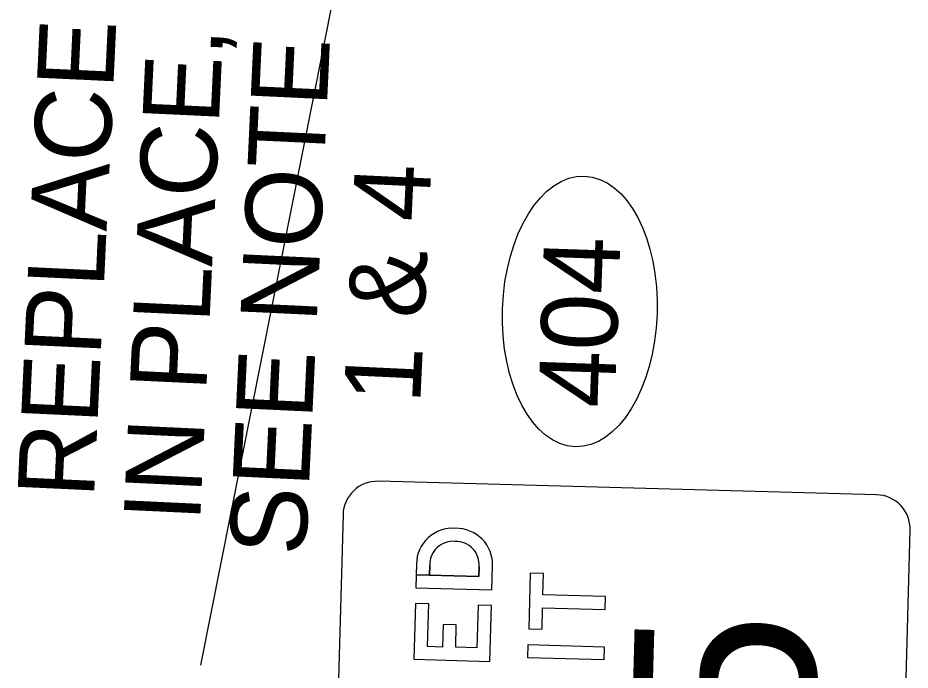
# Model space of a CAD drawing. Extents: x 2096670 to 2098561, y 684033 to 689893.
# Drawn here: x 2097308.7 to 2097448.6, y 687092.5 to 687194.8 of the extents above; entities that cross this region are included whole.
import ezdxf

# ---------------------------------------------------------------- set-up
doc = ezdxf.new("R2010")
doc.units = 0
for name, color, linetype in [('Prop DSN Text', 7, 'Continuous'), ('Prop Sign E Keep Right CELL', 7, 'Continuous'), ('Prop Sign E One Way_Right CELL', 7, 'Continuous'), ('Scratch_Level_3', 7, 'Continuous')]:
    doc.layers.add(name, color=color, linetype=linetype)

msp = doc.modelspace()

# ---------------------------------------------------------------- linework, layer by layer
at = {"layer": 'Prop Sign E Keep Right CELL'}
for p, q in [((2097443.4, 687120), (2097365.27, 687122.12)), ((2097359.73, 687116.87), (2097358.09, 687056.6)), ((2097447.01, 687054.19), (2097448.65, 687114.46)), ((2097381.02, 687107.2), (2097381.07, 687108.73)), ((2097383.05, 687105.09), (2097383.15, 687108.84))]:
    msp.add_line(p, q, dxfattribs=at)
for points in [[(2097371.25, 687109.17), (2097371.15, 687105.41), (2097383.05, 687105.09)], [(2097371.25, 687109.17), (2097371.2, 687107.46), (2097373.29, 687107.41), (2097373.33, 687108.94)], [(2097371.25, 687109.17), (2097371.2, 687107.46), (2097373.29, 687107.41), (2097373.33, 687108.94)], [(2097381.07, 687108.73), (2097381.02, 687107.2), (2097371.2, 687107.46), (2097371.15, 687105.41), (2097383.05, 687105.09), (2097383.15, 687108.84)], [(2097381.07, 687108.73), (2097381.02, 687107.2), (2097371.2, 687107.46), (2097371.15, 687105.41), (2097383.05, 687105.09), (2097383.15, 687108.84)], [(2097373.33, 687108.94), (2097373.29, 687107.41), (2097381.02, 687107.2)]]:
    msp.add_lwpolyline(points, dxfattribs=at)
for points in [[(2097390.93, 687098.92), (2097391.02, 687102.26), (2097400.84, 687102), (2097400.9, 687104.05), (2097391.07, 687104.31), (2097391.16, 687107.66), (2097389.08, 687107.71), (2097388.84, 687098.98)], [(2097390.93, 687098.92), (2097391.02, 687102.26), (2097400.84, 687102), (2097400.9, 687104.05), (2097391.07, 687104.31), (2097391.16, 687107.66), (2097389.08, 687107.71), (2097388.84, 687098.98)], [(2097390.93, 687098.92), (2097391.02, 687102.26), (2097400.84, 687102), (2097400.9, 687104.05), (2097391.07, 687104.31), (2097391.16, 687107.66), (2097389.08, 687107.71), (2097388.84, 687098.98)], [(2097380.9, 687102.68), (2097380.72, 687096), (2097377.4, 687096.09), (2097377.49, 687099.63), (2097375.41, 687099.69), (2097375.32, 687096.14), (2097372.98, 687096.21), (2097373.16, 687102.89), (2097371.08, 687102.95), (2097370.84, 687094.21), (2097382.75, 687093.89), (2097382.99, 687102.63)], [(2097380.9, 687102.68), (2097380.72, 687096), (2097377.4, 687096.09), (2097377.49, 687099.63), (2097375.41, 687099.69), (2097375.32, 687096.14), (2097372.98, 687096.21), (2097373.16, 687102.89), (2097371.08, 687102.95), (2097370.84, 687094.21), (2097382.75, 687093.89), (2097382.99, 687102.63)], [(2097380.9, 687102.68), (2097380.72, 687096), (2097377.4, 687096.09), (2097377.49, 687099.63), (2097375.41, 687099.69), (2097375.32, 687096.14), (2097372.98, 687096.21), (2097373.16, 687102.89), (2097371.08, 687102.95), (2097370.84, 687094.21), (2097382.75, 687093.89), (2097382.99, 687102.63)], [(2097400.63, 687094.14), (2097388.72, 687094.46), (2097388.78, 687096.51), (2097400.68, 687096.19)], [(2097400.63, 687094.14), (2097388.72, 687094.46), (2097388.78, 687096.51), (2097400.68, 687096.19)], [(2097400.63, 687094.14), (2097388.72, 687094.46), (2097388.78, 687096.51), (2097400.68, 687096.19)]]:
    msp.add_lwpolyline(points, close=True, dxfattribs=at)
for centre, start, end in [((2097365.12, 687116.72), 88.4491, 178.4491), ((2097443.25, 687114.61), 358.4491, 88.4491)]:
    msp.add_arc(centre, 5.4, start, end, dxfattribs=at)
for centre, major_axis, start_param, end_param in [((2097376.94, 687109.15), (-5.69, 0.15), 4.66648, 6.308552), ((2097376.94, 687109.15), (-5.69, 0.15), 4.66648, 6.308552), ((2097376.94, 687109.15), (-5.69, 0.15), 4.66648, 6.308552), ((2097377.46, 687109.14), (-5.69, 0.15), 3.116226, 4.758298), ((2097377.46, 687109.14), (-5.69, 0.15), 3.116226, 4.758298), ((2097377.46, 687109.14), (-5.69, 0.15), 3.116226, 4.758298), ((2097377.01, 687109.07), (-3.69, 0.1), 4.662786, 6.345315), ((2097377.01, 687109.07), (-3.69, 0.1), 4.662785, 6.345315), ((2097377.01, 687109.07), (-3.69, 0.1), 4.662785, 6.345315), ((2097377.38, 687109.06), (-3.69, 0.1), 3.079463, 4.761992), ((2097377.38, 687109.06), (-3.69, 0.1), 3.079463, 4.761992), ((2097377.38, 687109.06), (-3.69, 0.1), 3.079463, 4.761992)]:
    msp.add_ellipse(centre, major_axis=major_axis, ratio=0.985, start_param=start_param, end_param=end_param, dxfattribs=at)
at = {"layer": 'Prop Sign E One Way_Right CELL'}
msp.add_ellipse((2097396.85, 687148.75), major_axis=(-0.72, -21.21), ratio=0.571429, dxfattribs=at)
at = {"layer": 'Scratch_Level_3'}
msp.add_line((2097337.42, 687093.28), (2097363.65, 687225.08), dxfattribs=at)

# ---------------------------------------------------------------- texts
at = {"layer": 'Prop DSN Text'}
for s, p in [('REPLACE', (2097320.66, 687119.37)), ('IN PLACE,', (2097337.3, 687115.6)), ('SEE NOTE', (2097353.87, 687110.33)), ('1 & 4', (2097371.82, 687134.17))]:
    msp.add_text(s, height=12, rotation=87.2995, dxfattribs=at).set_placement(p)
at = {"layer": 'Prop Sign E Keep Right CELL'}
msp.add_text('45', height=28.584, rotation=88.4491, dxfattribs=at).set_placement((2097432.94, 687058.76))
at = {"layer": 'Prop Sign E One Way_Right CELL'}
msp.add_text('404', height=11.98, rotation=88.0434, dxfattribs=at).set_placement((2097402.32, 687133.53))

doc.saveas('drawing.dxf')
